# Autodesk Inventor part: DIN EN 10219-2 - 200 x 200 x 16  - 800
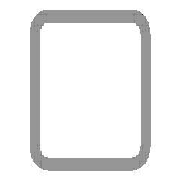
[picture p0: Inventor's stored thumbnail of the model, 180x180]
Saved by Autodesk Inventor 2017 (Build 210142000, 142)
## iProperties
Created: 2017-11
Part Number: DIN EN 10219-2 - 200 x 200 x 16  - 800
Material: Steel, Mild
Description: Cold formed welded structural hollow sections of non-alloy and fine grain structural steel
Document SubType Name: Modeling
Standard: DIN
Designer: iusti
Standard Revision: 2006-07
Standards Organization: DIN
Language: en-US
Size Designation: 200 x 200 x 16
Categories: <MemberInstance><Categories><Category DisplayName="Structural Shapes" InternalName="089c4875-fa83-4c05-b084-43b9cc11f5ed" Mnemonic="GRDR"><CategoryParameter Dis
Stock Number: 200 x 200 x 16
Mass: 67053.1 g
Surface Area: 10890.8 cm^2
Volume: 8541.79 cm^3
Density: 7.85 g/cm^3
Appearance: Semi-Polished
G_L: 800.000 mm
G_W: 200.000 mm
G_H: 200.000 mm
+FD70130C-4790-491E-B60B-C0D4A205CCEB+CUTDETAIL1: Cut
+AC41B5F9-E44C-4FA3-89BE-A85ECCB405C1+CUTDETAIL2: Cut
IsCustomPart: 1
_CCFamilyMember: 103
_CCFamilyDisplayName: DIN EN 10219-2 (Square Hollow Section - Cold Formed) - Cold formed welded structural hollow sections of non-alloy and fine grain structural steel
_FrameMemberDoc: Frame Member File
_Version: 15.0.0
_GetPNFromCC: 1
Author: iusti
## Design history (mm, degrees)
node "Start plane"
node "End plane"
sketch "Sketch"
  geometry: L1 (-100, -52)-(-100, 52); L2 (-52, 100)-(52, 100); L3 (100, 52)-(100, -52); L4 (52, -100)-(-52, -100); L5 (-52, 84)-(52, 84); L6 (84, 52)-(84, -52); L7 (52, -84)-(-52, -84); L8 (-84, -52)-(-84, 52); L9 (0, 153.918)-(0, -153.918) reference; L10 (-153.918, 0)-(153.918, 0) reference; A1 r 48 centre (-52, -52) between (-100, -52) and (-52, -100); A2 r 48 centre (-52, 52) between (-52, 100) and (-100, 52); A3 r 48 centre (52, 52) between (100, 52) and (52, 100); A4 r 48 centre (52, -52) between (52, -100) and (100, -52); A5 r 32 centre (-52, 52) between (-52, 84) and (-84, 52); A6 r 32 centre (52, 52) between (84, 52) and (52, 84); A7 r 32 centre (52, -52) between (52, -84) and (84, -52); A8 r 32 centre (-52, -52) between (-84, -52) and (-52, -84)
  constraints: 16 end point, 16 point on circle, 8 centre point, 8 tangent, 4 parallel, 3 equal radius, 2 perpendicular, 7 other
  dimensions: "d7" = 48 radius of A1 (= G_IR); "d10" = 200 distance between parallel lines of L2 L4 (= G_H); "d11" = 200 distance between parallel lines of L1 L3 (= G_W); "d12" = 16 distance between parallel lines of L3 L6 (= G_T); "d15" = 100 distance between parallel lines of L2 L10 (= 0.5 x d10); "d16" = 100 distance between parallel lines of L9 L3 (= 0.5 x d11)
extrude "Body" new body sketch "Sketch" stored distance "d3" = 800 (= G_L); taper "d4" = 0 deg
node "Driven Length"
  sketch "Sketch3"
    geometry: L1 (0, 0)-(10, 0) reference
    constraints: 2 end point, 1 horizontal
  workplane "Work Plane3"
  sketch "Sketch4"
    geometry: L1 (-2, 100)-(12, 100) reference; L2 (-2, 900)-(12, 900) reference
    dimensions: "d18" = 800 distance between parallel lines of L1 L2 (derived)
workplane "Work Plane4"
split "Split1"
workplane "Work Plane5"
split "Split2"
body "Solid1"
other parameters: "G_W" = 200 [user parameter; used in 1 equation term], "G_H" = 200 [user parameter; used in 1 equation term], "G_T" = 16 [user parameter; used in 1 equation term], "G_IR" = 48 [user parameter; used in 1 equation term], "G_L" = 800 (= d18) [user parameter; used in 1 equation term], "d17" = 90 deg
